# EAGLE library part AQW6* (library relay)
PhotoMOS Relay NAiS Source: http://www.mew-europe.com/.. pti_en.pdf
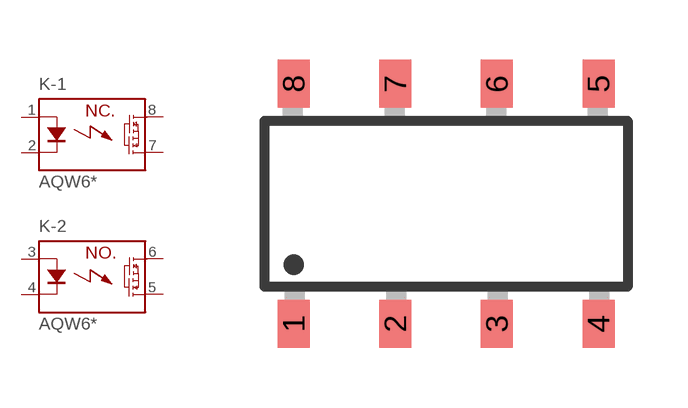
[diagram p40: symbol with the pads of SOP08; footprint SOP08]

Designator prefix K; gates -1=PHOTOMOS_2D_NC -2=PHOTOMOS_2D_NO

## AQW61SOP (OC_FARNELL: unknown; OC_NEWARK: unknown)  [SOP08]
1  -1:A  pas
2  -1:K  pas
3  -2:A  pas
4  -2:K  pas
5  -2:DS2  pas
6  -2:DS1  pas
7  -1:DS2  pas
8  -1:DS1  pas

## Footprint SOP08 (pad centres in mm)
SOP 08 - AQW21, AQW61 Series NAiS Source: http://www.mew-europe.com/.. pti_en.pdf
smd 0.8 x 1.2: 1 -3.81,-3; 2 -1.27,-3; 3 1.27,-3; 4 3.81,-3; 5 3.81,3; 6 1.27,3; 7 -1.27,3; 8 -3.81,3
